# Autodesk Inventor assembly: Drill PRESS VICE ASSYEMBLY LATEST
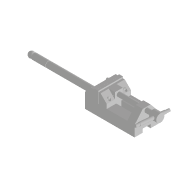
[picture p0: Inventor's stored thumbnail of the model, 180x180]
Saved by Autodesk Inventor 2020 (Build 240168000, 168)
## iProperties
Created: 2019-04
Part Number: Drill PRESS VICE ASSYEMBLY LATEST
Document SubType Name: Assembly
Designer: LENOVO-CADCIM
Author: LENOVO-CADCIM
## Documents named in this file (8)
- D:\Autodesk Inventor_2020\c10\c10_Inv_2019_tut\c10_Inv_tut_2019\c10_tut02_inv\Drill Press Vice\Drill Press Vice\Drill PRESS VICE ASSYEMBLY LATEST.iam
- D:\Autodesk Inventor_2020\c10\c10_Inv_2019_tut\c10_Inv_tut_2019\c10_tut02_inv\Drill Press Vice\Drill Press Vice\Base.ipt
- D:\Autodesk Inventor_2020\c10\c10_Inv_2019_tut\c10_Inv_tut_2019\c10_tut02_inv\Drill Press Vice\Drill Press Vice\Movable Jaw.ipt
- D:\Autodesk Inventor_2020\c10\c10_Inv_2019_tut\c10_Inv_tut_2019\c10_tut02_inv\Drill Press Vice\Drill Press Vice\Jaw Face.ipt
- D:\Autodesk Inventor_2020\c10\c10_Inv_2019_tut\c10_Inv_tut_2019\c10_tut02_inv\Drill Press Vice\Drill Press Vice\Cap Screw.ipt
- D:\Autodesk Inventor_2020\c10\c10_Inv_2019_tut\c10_Inv_tut_2019\c10_tut02_inv\Drill Press Vice\Drill Press Vice\Clamp Screw Handle.ipt
- D:\Autodesk Inventor_2020\c10\c10_Inv_2019_tut\c10_Inv_tut_2019\c10_tut02_inv\Drill Press Vice\Drill Press Vice\Clamp Screw.ipt
- D:\Autodesk Inventor_2020\c10\c10_Inv_2019_tut\c10_Inv_tut_2019\c10_tut02_inv\Drill Press Vice\Drill Press Vice\Safety Handle.ipt
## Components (11 placed, 7 different names)
1. Base:1 — Mate:1, Mate:2, Insert:1, Insert:4, Insert:5, Mate:3, Mate:6, Mate:7
2. Movable Jaw:1 — Mate:1, Mate:2, Insert:2, Insert:3, Insert:6, Insert:7, Mate:4
3. Jaw Face:1 — Insert:1, Mate:8
4. Jaw Face:2 — Insert:2, Insert:3, Mate:8
5. Cap Screw:1 — Insert:4
6. Cap Screw:2 — Insert:7
7. Cap Screw:3 — Insert:5
8. Cap Screw:4 — Insert:6
9. Clamp Screw Handle:1 — Mate:5
10. Clamp Screw:1 — Mate:3, Mate:4, Mate:5
11. Safety Handle:1 — Mate:6, Mate:7
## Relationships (15: Mate 8, Insert 7)
- Mate:1: Base:1 ↔ Movable Jaw:1
- Mate:2: Base:1 ↔ Movable Jaw:1
- Insert:1: Base:1 ↔ Jaw Face:1
- Insert:2: Movable Jaw:1 ↔ Jaw Face:2
- Insert:3: Movable Jaw:1 ↔ Jaw Face:2
- Insert:4: Base:1 ↔ Cap Screw:1
- Insert:5: Base:1 ↔ Cap Screw:3
- Insert:6: Movable Jaw:1 ↔ Cap Screw:4
- Insert:7: Movable Jaw:1 ↔ Cap Screw:2
- Mate:3: Base:1 ↔ Clamp Screw:1
- Mate:4: Movable Jaw:1 ↔ Clamp Screw:1
- Mate:5: Clamp Screw Handle:1 ↔ Clamp Screw:1
- Mate:6: Base:1 ↔ Safety Handle:1
- Mate:7: Base:1 ↔ Safety Handle:1
- Mate:8: Jaw Face:1 ↔ Jaw Face:2
